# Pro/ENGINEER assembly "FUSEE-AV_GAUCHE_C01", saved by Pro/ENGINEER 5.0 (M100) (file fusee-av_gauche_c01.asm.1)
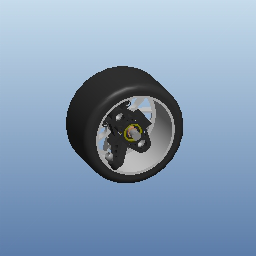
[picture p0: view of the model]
Units: millimeter Newton Second (mmNs); MM, TONNE, HOURS

Other components: ENTRETOISE_8X13, RONDELLE_PLATE-D6, ECROU_HFR_M6, ROULEMENT_BC_8X22X7, 80655614-CARRE_ROUE_14_C01, ROULEMENT_BC_8X22X7, ECROU_SPHER-M15, ROUE_V0_C01, E-ROTULE_VIS_C02, ECROU_SPHER-M15, VIS_CHC_M-4X16, 80351300-AXE_ROUE_AV_LG_C01, 80657500-FUSEE_AV_DEPORT_C01, 80650400-LEVIER_FUSEE_AV_C01

Other named items: A-DROITE, A-DESSUS, A-FACE, A-R0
